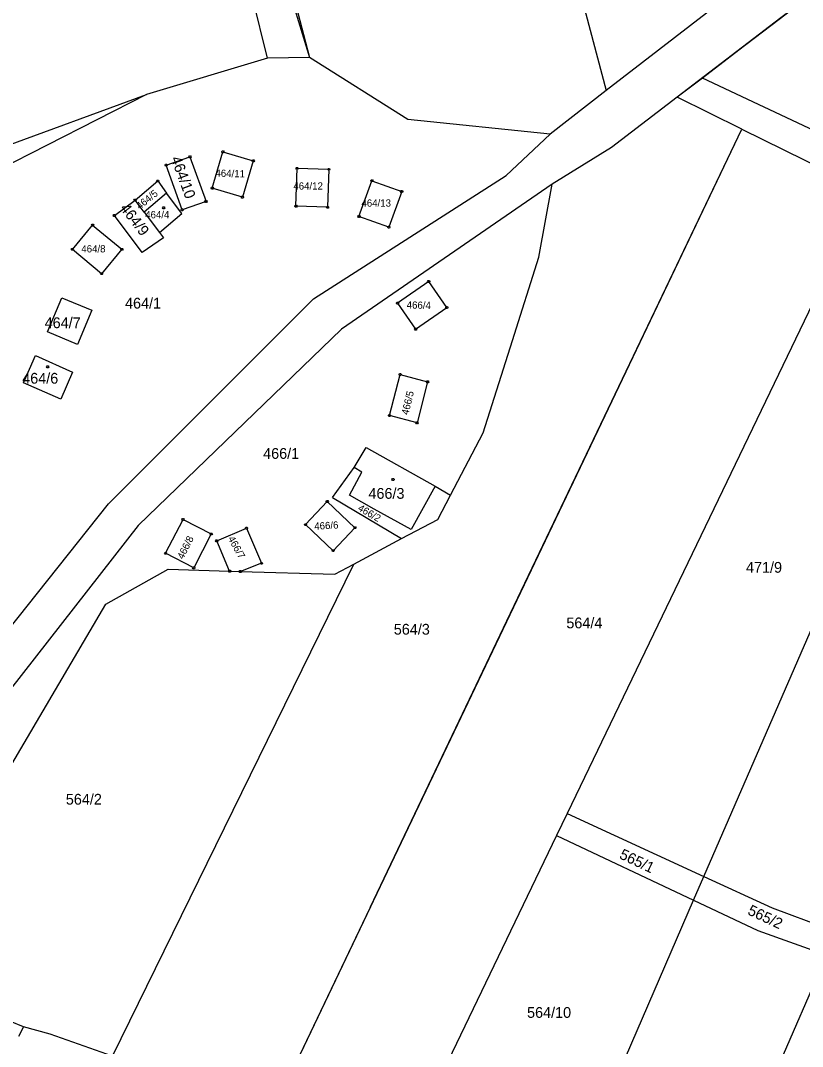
# Model space of a CAD drawing. Extents: x -634640 to -629202, y -1196156 to -1190068.
# Drawn here: x -631485.4 to -631362, y -1192430.1 to -1192268.2 of the extents above; entities that cross this region are included whole.
import ezdxf

# ---------------------------------------------------------------- set-up
doc = ezdxf.new("R2010")
doc.units = 0
for name, color, linetype in [('Obvod převzatý', 7, 'Continuous'), ('Obvod šetřený', 7, 'Continuous'), ('Vrstva 1', 7, 'Continuous'), ('Vrstva 2', 7, 'Continuous'), ('Vrstva 5', 7, 'Continuous'), ('Vrstva 8', 7, 'Continuous')]:
    doc.layers.add(name, color=color, linetype=linetype)

msp = doc.modelspace()

# ---------------------------------------------------------------- linework, layer by layer
at = {"layer": 'Obvod převzatý'}
for points in [[(-631430.186, -1192408.103), (-631408.66, -1192362.97), (-631371.62, -1192285.31), (-631376.7, -1192282.805), (-631381.78, -1192280.3)], [(-631430.186, -1192408.103), (-631445.7, -1192440.63)]]:
    msp.add_lwpolyline(points, dxfattribs=at)
at = {"layer": 'Obvod šetřený'}
for points in [[(-631616.29, -1192112.25), (-631606.99, -1192117.845), (-631603.89, -1192119.71), (-631598.89, -1192123.93), (-631590.975, -1192122.16), (-631583.06, -1192120.39), (-631541.795, -1192107.135), (-631500.53, -1192093.88), (-631453.411, -1192078.742), (-631446.68, -1192076.58), (-631437.445, -1192073.613), (-631409.74, -1192064.71), (-631403.208, -1192088.114), (-631396.675, -1192111.518), (-631390.142, -1192134.921), (-631383.61, -1192158.325), (-631377.078, -1192181.729), (-631370.545, -1192205.133), (-631364.013, -1192228.536), (-631357.48, -1192251.94), (-631352.735, -1192253.235), (-631347.99, -1192254.53), (-631365.44, -1192267.77), (-631381.78, -1192280.3)], [(-631598.89, -1192123.93), (-631590.975, -1192122.16), (-631583.06, -1192120.39), (-631541.795, -1192107.135), (-631521.162, -1192100.508), (-631500.53, -1192093.88), (-631476.971, -1192086.311), (-631450.046, -1192077.661), (-631437.445, -1192073.613), (-631423.593, -1192069.161), (-631409.74, -1192064.71), (-631383.61, -1192158.325), (-631364.013, -1192228.536), (-631360.746, -1192240.238), (-631357.48, -1192251.94), (-631350.363, -1192253.883), (-631347.99, -1192254.53), (-631356.715, -1192261.15), (-631373.61, -1192274.035), (-631377.82, -1192277.27), (-631381.78, -1192280.3)]]:
    msp.add_lwpolyline(points, dxfattribs=at)
at = {"layer": 'Vrstva 1'}
for p, q in [((-631446.68, -1192076.58), (-631393, -1192279.25)), ((-631475.58, -1192137.37), (-631439.81, -1192274.04)), ((-631478.78, -1192147.06), (-631439.81, -1192274.04)), ((-631446.44, -1192274.14), (-631456.24, -1192234.82)), ((-631366.96, -1192259.1), (-631393, -1192279.25)), ((-631365.44, -1192267.77), (-631377.82, -1192277.27)), ((-631439.81, -1192274.04), (-631446.44, -1192274.14)), ((-631424.33, -1192283.78), (-631439.81, -1192274.04)), ((-631446.44, -1192274.14), (-631465.53, -1192279.88)), ((-631377.82, -1192277.27), (-631381.78, -1192280.3)), ((-631349.71, -1192290.55), (-631377.82, -1192277.27)), ((-631526.81, -1192302.22), (-631465.53, -1192279.88)), ((-631465.53, -1192279.88), (-631490.22, -1192292.44)), ((-631393, -1192279.25), (-631401.86, -1192286.1)), ((-631381.78, -1192280.3), (-631392.15, -1192288.25)), ((-631371.62, -1192285.31), (-631381.78, -1192280.3)), ((-631401.86, -1192286.1), (-631424.33, -1192283.78)), ((-631445.7, -1192440.63), (-631371.62, -1192285.31)), ((-631371.62, -1192285.31), (-631351.89, -1192295.05)), ((-631408.8, -1192292.64), (-631401.86, -1192286.1)), ((-631392.15, -1192288.25), (-631401.51, -1192294.01)), ((-631462.45, -1192291.02), (-631458.69, -1192289.69)), ((-631458.69, -1192289.69), (-631456.15, -1192296.75)), ((-631455.18, -1192294.66), (-631453.5, -1192288.9)), ((-631453.5, -1192288.9), (-631448.71, -1192290.32)), ((-631448.71, -1192290.32), (-631450.41, -1192296.07)), ((-631459.92, -1192298.08), (-631462.45, -1192291.02)), ((-631441.98, -1192297.5), (-631441.79, -1192291.51)), ((-631441.79, -1192291.51), (-631436.78, -1192291.67)), ((-631436.78, -1192291.67), (-631436.98, -1192297.67)), ((-631439.17, -1192312.11), (-631408.8, -1192292.64)), ((-631432.02, -1192299.11), (-631429.98, -1192293.47)), ((-631429.98, -1192293.47), (-631425.26, -1192295.17)), ((-631450.41, -1192296.07), (-631455.18, -1192294.66)), ((-631401.51, -1192294.01), (-631434.8, -1192316.91)), ((-631425.26, -1192295.17), (-631427.31, -1192300.82)), ((-631403.64, -1192305.55), (-631401.51, -1192294.01)), ((-631351.89, -1192295.05), (-631399.18, -1192393.38)), ((-631470.62, -1192298.98), (-631467.35, -1192296.52)), ((-631465.93, -1192298.41), (-631467.35, -1192296.52)), ((-631462.37, -1192295.41), (-631465.93, -1192298.41)), ((-631459.98, -1192298.64), (-631462.37, -1192295.41)), ((-631456.15, -1192296.75), (-631459.92, -1192298.08)), ((-631465.93, -1192298.41), (-631463.52, -1192301.62)), ((-631436.98, -1192297.67), (-631441.98, -1192297.5)), ((-631466.26, -1192304.81), (-631470.62, -1192298.98)), ((-631463.52, -1192301.62), (-631459.98, -1192298.64)), ((-631427.31, -1192300.82), (-631432.02, -1192299.11)), ((-631477.25, -1192304.31), (-631474.06, -1192300.47)), ((-631474.06, -1192300.47), (-631469.44, -1192304.3)), ((-631463.52, -1192301.62), (-631462.85, -1192302.5)), ((-631462.85, -1192302.5), (-631466.26, -1192304.81)), ((-631377.58, -1192403.32), (-631334.04, -1192302.96)), ((-631472.64, -1192308.15), (-631477.25, -1192304.31)), ((-631469.44, -1192304.3), (-631472.64, -1192308.15)), ((-631407.77, -1192318.71), (-631403.64, -1192305.55)), ((-631421, -1192309.38), (-631425.93, -1192312.8)), ((-631418.15, -1192313.49), (-631421, -1192309.38)), ((-631481.18, -1192317.32), (-631478.92, -1192311.94)), ((-631478.92, -1192311.94), (-631474.17, -1192313.93)), ((-631471.55, -1192344.46), (-631439.17, -1192312.11)), ((-631425.93, -1192312.8), (-631423.08, -1192316.91)), ((-631474.17, -1192313.93), (-631476.44, -1192319.31)), ((-631423.08, -1192316.91), (-631418.15, -1192313.49)), ((-631476.44, -1192319.31), (-631481.18, -1192317.32)), ((-631434.8, -1192316.91), (-631466.86, -1192347.91)), ((-631412.4, -1192333.27), (-631407.77, -1192318.71)), ((-631484.95, -1192325.37), (-631483.07, -1192321.08)), ((-631483.07, -1192321.08), (-631477.21, -1192323.67)), ((-631477.21, -1192323.67), (-631479.09, -1192327.96)), ((-631427.2, -1192330.55), (-631425.52, -1192324.08)), ((-631425.52, -1192324.08), (-631421.18, -1192325.21)), ((-631479.09, -1192327.96), (-631484.95, -1192325.37)), ((-631421.18, -1192325.21), (-631422.86, -1192331.68)), ((-631422.86, -1192331.68), (-631427.2, -1192330.55)), ((-631417.59, -1192343.11), (-631412.4, -1192333.27)), ((-631432.76, -1192338.75), (-631430.88, -1192335.59)), ((-631430.88, -1192335.59), (-631420.01, -1192341.69)), ((-631436.2, -1192343.46), (-631432.76, -1192338.75)), ((-631420.01, -1192341.69), (-631417.59, -1192343.11)), ((-631436.2, -1192343.46), (-631425.29, -1192349.97)), ((-631419.6, -1192346.93), (-631417.59, -1192343.11)), ((-631498.14, -1192377.93), (-631471.55, -1192344.46)), ((-631440.46, -1192347.77), (-631437.03, -1192344.13)), ((-631437.03, -1192344.13), (-631432.66, -1192348.25)), ((-631462.54, -1192352.29), (-631459.79, -1192346.95)), ((-631459.79, -1192346.95), (-631455.34, -1192349.24)), ((-631425.29, -1192349.97), (-631419.6, -1192346.93)), ((-631466.86, -1192347.91), (-631512.45, -1192406.32)), ((-631454.46, -1192350.34), (-631449.77, -1192348.34)), ((-631449.77, -1192348.34), (-631447.4, -1192353.87)), ((-631436.09, -1192351.88), (-631440.46, -1192347.77)), ((-631432.66, -1192348.25), (-631436.09, -1192351.88)), ((-631455.34, -1192349.24), (-631458.09, -1192354.57)), ((-631432.82, -1192354), (-631425.29, -1192349.97)), ((-631452.43, -1192355.1), (-631454.46, -1192350.34)), ((-631458.09, -1192354.57), (-631462.54, -1192352.29)), ((-631471.97, -1192360.34), (-631462.12, -1192354.81)), ((-631470.93, -1192431.68), (-631432.82, -1192354)), ((-631462.12, -1192354.81), (-631452.43, -1192355.1)), ((-631452.43, -1192355.1), (-631450.74, -1192355.15)), ((-631447.4, -1192353.87), (-631450.74, -1192355.15)), ((-631435.82, -1192355.6), (-631432.82, -1192354)), ((-631450.74, -1192355.15), (-631435.82, -1192355.6)), ((-631487.31, -1192386.45), (-631471.97, -1192360.34)), ((-631399.18, -1192393.38), (-631400.85, -1192396.86)), ((-631399.18, -1192393.38), (-631377.58, -1192403.32)), ((-631400.85, -1192396.86), (-631423.45, -1192443.85)), ((-631400.85, -1192396.86), (-631379.2, -1192407.07)), ((-631379.2, -1192407.07), (-631377.58, -1192403.32)), ((-631377.58, -1192403.32), (-631366.8, -1192408.28)), ((-631399.95, -1192454.9), (-631379.2, -1192407.07)), ((-631379.2, -1192407.07), (-631369.06, -1192411.86)), ((-631366.8, -1192408.28), (-631356.64, -1192412.09)), ((-631369.06, -1192411.86), (-631358.23, -1192415.75)), ((-631379.4, -1192464.56), (-631358.23, -1192415.75)), ((-631484.94, -1192427.03), (-631509.66, -1192417.1)), ((-631484.94, -1192427.03), (-631485.75, -1192428.57)), ((-631480.78, -1192428.21), (-631484.94, -1192427.03)), ((-631470.93, -1192431.68), (-631480.78, -1192428.21))]:
    msp.add_line(p, q, dxfattribs=at)
for points in [[(-631467.35, -1192296.52), (-631463.77, -1192293.51), (-631462.37, -1192295.41)], [(-631420.01, -1192341.69), (-631423.78, -1192348.51), (-631429.64, -1192345.34), (-631433.5, -1192343.11), (-631431.56, -1192339.49), (-631432.76, -1192338.75)]]:
    msp.add_lwpolyline(points, dxfattribs=at)
at = {"layer": 'Vrstva 5'}
for points in [[(-631462.75, -1192297.59), (-631462.66, -1192297.74), (-631462.75, -1192297.89), (-631462.93, -1192297.89), (-631463.02, -1192297.74), (-631462.93, -1192297.59), (-631462.75, -1192297.59)], [(-631481.07, -1192322.72), (-631480.98, -1192322.87), (-631481.07, -1192323.02), (-631481.25, -1192323.02), (-631481.34, -1192322.87), (-631481.25, -1192322.72), (-631481.07, -1192322.72)], [(-631426.54, -1192340.49), (-631426.45, -1192340.64), (-631426.54, -1192340.79), (-631426.72, -1192340.79), (-631426.81, -1192340.64), (-631426.72, -1192340.49), (-631426.54, -1192340.49)]]:
    msp.add_lwpolyline(points, dxfattribs=at)
at = {"layer": 'Vrstva 8'}
for points in [[(-631458.6, -1192289.54), (-631458.51, -1192289.69), (-631458.6, -1192289.84), (-631458.78, -1192289.84), (-631458.87, -1192289.69), (-631458.78, -1192289.54), (-631458.6, -1192289.54)], [(-631453.41, -1192288.75), (-631453.32, -1192288.9), (-631453.41, -1192289.05), (-631453.59, -1192289.05), (-631453.68, -1192288.9), (-631453.59, -1192288.75), (-631453.41, -1192288.75)], [(-631448.62, -1192290.17), (-631448.53, -1192290.32), (-631448.62, -1192290.47), (-631448.8, -1192290.47), (-631448.89, -1192290.32), (-631448.8, -1192290.17), (-631448.62, -1192290.17)], [(-631462.36, -1192290.87), (-631462.27, -1192291.02), (-631462.36, -1192291.17), (-631462.54, -1192291.17), (-631462.63, -1192291.02), (-631462.54, -1192290.87), (-631462.36, -1192290.87)], [(-631441.7, -1192291.36), (-631441.61, -1192291.51), (-631441.7, -1192291.66), (-631441.88, -1192291.66), (-631441.97, -1192291.51), (-631441.88, -1192291.36), (-631441.7, -1192291.36)], [(-631436.69, -1192291.52), (-631436.6, -1192291.67), (-631436.69, -1192291.82), (-631436.87, -1192291.82), (-631436.96, -1192291.67), (-631436.87, -1192291.52), (-631436.69, -1192291.52)], [(-631463.68, -1192293.36), (-631463.59, -1192293.51), (-631463.68, -1192293.66), (-631463.86, -1192293.66), (-631463.95, -1192293.51), (-631463.86, -1192293.36), (-631463.68, -1192293.36)], [(-631429.89, -1192293.32), (-631429.8, -1192293.47), (-631429.89, -1192293.62), (-631430.07, -1192293.62), (-631430.16, -1192293.47), (-631430.07, -1192293.32), (-631429.89, -1192293.32)], [(-631455.09, -1192294.51), (-631455, -1192294.66), (-631455.09, -1192294.81), (-631455.27, -1192294.81), (-631455.36, -1192294.66), (-631455.27, -1192294.51), (-631455.09, -1192294.51)], [(-631425.17, -1192295.02), (-631425.08, -1192295.17), (-631425.17, -1192295.32), (-631425.35, -1192295.32), (-631425.44, -1192295.17), (-631425.35, -1192295.02), (-631425.17, -1192295.02)], [(-631467.26, -1192296.37), (-631467.17, -1192296.52), (-631467.26, -1192296.67), (-631467.44, -1192296.67), (-631467.53, -1192296.52), (-631467.44, -1192296.37), (-631467.26, -1192296.37)], [(-631456.06, -1192296.6), (-631455.97, -1192296.75), (-631456.06, -1192296.9), (-631456.24, -1192296.9), (-631456.33, -1192296.75), (-631456.24, -1192296.6), (-631456.06, -1192296.6)], [(-631450.32, -1192295.92), (-631450.23, -1192296.07), (-631450.32, -1192296.22), (-631450.5, -1192296.22), (-631450.59, -1192296.07), (-631450.5, -1192295.92), (-631450.32, -1192295.92)], [(-631459.83, -1192297.93), (-631459.74, -1192298.08), (-631459.83, -1192298.23), (-631460.01, -1192298.23), (-631460.1, -1192298.08), (-631460.01, -1192297.93), (-631459.83, -1192297.93)], [(-631441.89, -1192297.35), (-631441.8, -1192297.5), (-631441.89, -1192297.65), (-631442.07, -1192297.65), (-631442.16, -1192297.5), (-631442.07, -1192297.35), (-631441.89, -1192297.35)], [(-631436.89, -1192297.52), (-631436.8, -1192297.67), (-631436.89, -1192297.82), (-631437.07, -1192297.82), (-631437.16, -1192297.67), (-631437.07, -1192297.52), (-631436.89, -1192297.52)], [(-631470.53, -1192298.83), (-631470.44, -1192298.98), (-631470.53, -1192299.13), (-631470.71, -1192299.13), (-631470.8, -1192298.98), (-631470.71, -1192298.83), (-631470.53, -1192298.83)], [(-631431.93, -1192298.96), (-631431.84, -1192299.11), (-631431.93, -1192299.26), (-631432.11, -1192299.26), (-631432.2, -1192299.11), (-631432.11, -1192298.96), (-631431.93, -1192298.96)], [(-631473.97, -1192300.32), (-631473.88, -1192300.47), (-631473.97, -1192300.62), (-631474.15, -1192300.62), (-631474.24, -1192300.47), (-631474.15, -1192300.32), (-631473.97, -1192300.32)], [(-631427.22, -1192300.67), (-631427.13, -1192300.82), (-631427.22, -1192300.97), (-631427.4, -1192300.97), (-631427.49, -1192300.82), (-631427.4, -1192300.67), (-631427.22, -1192300.67)], [(-631477.16, -1192304.16), (-631477.07, -1192304.31), (-631477.16, -1192304.46), (-631477.34, -1192304.46), (-631477.43, -1192304.31), (-631477.34, -1192304.16), (-631477.16, -1192304.16)], [(-631469.35, -1192304.15), (-631469.26, -1192304.3), (-631469.35, -1192304.45), (-631469.53, -1192304.45), (-631469.62, -1192304.3), (-631469.53, -1192304.15), (-631469.35, -1192304.15)], [(-631472.55, -1192308), (-631472.46, -1192308.15), (-631472.55, -1192308.3), (-631472.73, -1192308.3), (-631472.82, -1192308.15), (-631472.73, -1192308), (-631472.55, -1192308)], [(-631420.91, -1192309.23), (-631420.82, -1192309.38), (-631420.91, -1192309.53), (-631421.09, -1192309.53), (-631421.18, -1192309.38), (-631421.09, -1192309.23), (-631420.91, -1192309.23)], [(-631425.84, -1192312.65), (-631425.75, -1192312.8), (-631425.84, -1192312.95), (-631426.02, -1192312.95), (-631426.11, -1192312.8), (-631426.02, -1192312.65), (-631425.84, -1192312.65)], [(-631418.06, -1192313.34), (-631417.97, -1192313.49), (-631418.06, -1192313.64), (-631418.24, -1192313.64), (-631418.33, -1192313.49), (-631418.24, -1192313.34), (-631418.06, -1192313.34)], [(-631422.99, -1192316.76), (-631422.9, -1192316.91), (-631422.99, -1192317.06), (-631423.17, -1192317.06), (-631423.26, -1192316.91), (-631423.17, -1192316.76), (-631422.99, -1192316.76)], [(-631425.43, -1192323.93), (-631425.34, -1192324.08), (-631425.43, -1192324.23), (-631425.61, -1192324.23), (-631425.7, -1192324.08), (-631425.61, -1192323.93), (-631425.43, -1192323.93)], [(-631421.09, -1192325.06), (-631421, -1192325.21), (-631421.09, -1192325.36), (-631421.27, -1192325.36), (-631421.36, -1192325.21), (-631421.27, -1192325.06), (-631421.09, -1192325.06)], [(-631427.11, -1192330.4), (-631427.02, -1192330.55), (-631427.11, -1192330.7), (-631427.29, -1192330.7), (-631427.38, -1192330.55), (-631427.29, -1192330.4), (-631427.11, -1192330.4)], [(-631422.77, -1192331.53), (-631422.68, -1192331.68), (-631422.77, -1192331.83), (-631422.95, -1192331.83), (-631423.04, -1192331.68), (-631422.95, -1192331.53), (-631422.77, -1192331.53)], [(-631436.94, -1192343.98), (-631436.85, -1192344.13), (-631436.94, -1192344.28), (-631437.12, -1192344.28), (-631437.21, -1192344.13), (-631437.12, -1192343.98), (-631436.94, -1192343.98)], [(-631459.7, -1192346.8), (-631459.61, -1192346.95), (-631459.7, -1192347.1), (-631459.88, -1192347.1), (-631459.97, -1192346.95), (-631459.88, -1192346.8), (-631459.7, -1192346.8)], [(-631449.68, -1192348.19), (-631449.59, -1192348.34), (-631449.68, -1192348.49), (-631449.86, -1192348.49), (-631449.95, -1192348.34), (-631449.86, -1192348.19), (-631449.68, -1192348.19)], [(-631440.37, -1192347.62), (-631440.28, -1192347.77), (-631440.37, -1192347.92), (-631440.55, -1192347.92), (-631440.64, -1192347.77), (-631440.55, -1192347.62), (-631440.37, -1192347.62)], [(-631432.57, -1192348.1), (-631432.48, -1192348.25), (-631432.57, -1192348.4), (-631432.75, -1192348.4), (-631432.84, -1192348.25), (-631432.75, -1192348.1), (-631432.57, -1192348.1)], [(-631455.25, -1192349.09), (-631455.16, -1192349.24), (-631455.25, -1192349.39), (-631455.43, -1192349.39), (-631455.52, -1192349.24), (-631455.43, -1192349.09), (-631455.25, -1192349.09)], [(-631454.37, -1192350.19), (-631454.28, -1192350.34), (-631454.37, -1192350.49), (-631454.55, -1192350.49), (-631454.64, -1192350.34), (-631454.55, -1192350.19), (-631454.37, -1192350.19)], [(-631436, -1192351.73), (-631435.91, -1192351.88), (-631436, -1192352.03), (-631436.18, -1192352.03), (-631436.27, -1192351.88), (-631436.18, -1192351.73), (-631436, -1192351.73)], [(-631462.45, -1192352.14), (-631462.36, -1192352.29), (-631462.45, -1192352.44), (-631462.63, -1192352.44), (-631462.72, -1192352.29), (-631462.63, -1192352.14), (-631462.45, -1192352.14)], [(-631458, -1192354.42), (-631457.91, -1192354.57), (-631458, -1192354.72), (-631458.18, -1192354.72), (-631458.27, -1192354.57), (-631458.18, -1192354.42), (-631458, -1192354.42)], [(-631452.34, -1192354.95), (-631452.25, -1192355.1), (-631452.34, -1192355.25), (-631452.52, -1192355.25), (-631452.61, -1192355.1), (-631452.52, -1192354.95), (-631452.34, -1192354.95)], [(-631450.65, -1192355), (-631450.56, -1192355.15), (-631450.65, -1192355.3), (-631450.83, -1192355.3), (-631450.92, -1192355.15), (-631450.83, -1192355), (-631450.65, -1192355)], [(-631447.31, -1192353.72), (-631447.22, -1192353.87), (-631447.31, -1192354.02), (-631447.49, -1192354.02), (-631447.58, -1192353.87), (-631447.49, -1192353.72), (-631447.31, -1192353.72)]]:
    msp.add_lwpolyline(points, dxfattribs=at)

# ---------------------------------------------------------------- texts
at = {"layer": 'Vrstva 2'}
for s, height, rotation, p in [('464/10', 1.7, 290.20312, (-631461.738, -1192289.949)), ('464/11', 1.14, 358.49969, (-631454.683, -1192292.829)), ('464/5', 1.14, 38.78924, (-631466.614, -1192298.079)), ('464/9', 1.7, 307.56374, (-631469.813, -1192297.842)), ('466/4', 1.14, 358.61428, (-631424.5, -1192313.637)), ('466/5', 1.14, 76.37528, (-631424.231, -1192330.521)), ('466/2', 1.14, 329.79451, (-631432.302, -1192345.465)), ('466/6', 1.14, 3.38045, (-631439.043, -1192348.591)), ('466/8', 1.14, 63.59831, (-631459.753, -1192353.323)), ('466/7', 1.14, 298.6256, (-631452.735, -1192349.949)), ('565/1', 1.7, 334.49276, (-631391.056, -1192400.392)), ('565/2', 1.7, 334.77924, (-631370.815, -1192409.241))]:
    msp.add_text(s, height=height, rotation=rotation, dxfattribs=at).set_placement(p)
for s, height, p in [('464/12', 1.14, (-631442.371, -1192294.87)), ('464/13', 1.14, (-631431.631, -1192297.56)), ('464/4', 1.14, (-631465.755, -1192299.4)), ('464/8', 1.14, (-631475.838, -1192304.79)), ('464/1', 1.7, (-631468.94, -1192313.65)), ('464/7', 1.7, (-631481.625, -1192316.75)), ('464/6', 1.7, (-631485.168, -1192325.51)), ('466/1', 1.7, (-631447.143, -1192337.38)), ('466/3', 1.7, (-631430.528, -1192343.69)), ('471/9', 1.7, (-631370.943, -1192355.36)), ('564/4', 1.7, (-631399.293, -1192364.13)), ('564/3', 1.7, (-631426.523, -1192365.13)), ('564/2', 1.7, (-631478.283, -1192391.97)), ('564/10', 1.7, (-631405.493, -1192425.63))]:
    msp.add_text(s, height=height, dxfattribs=at).set_placement(p)

doc.saveas('drawing.dxf')
